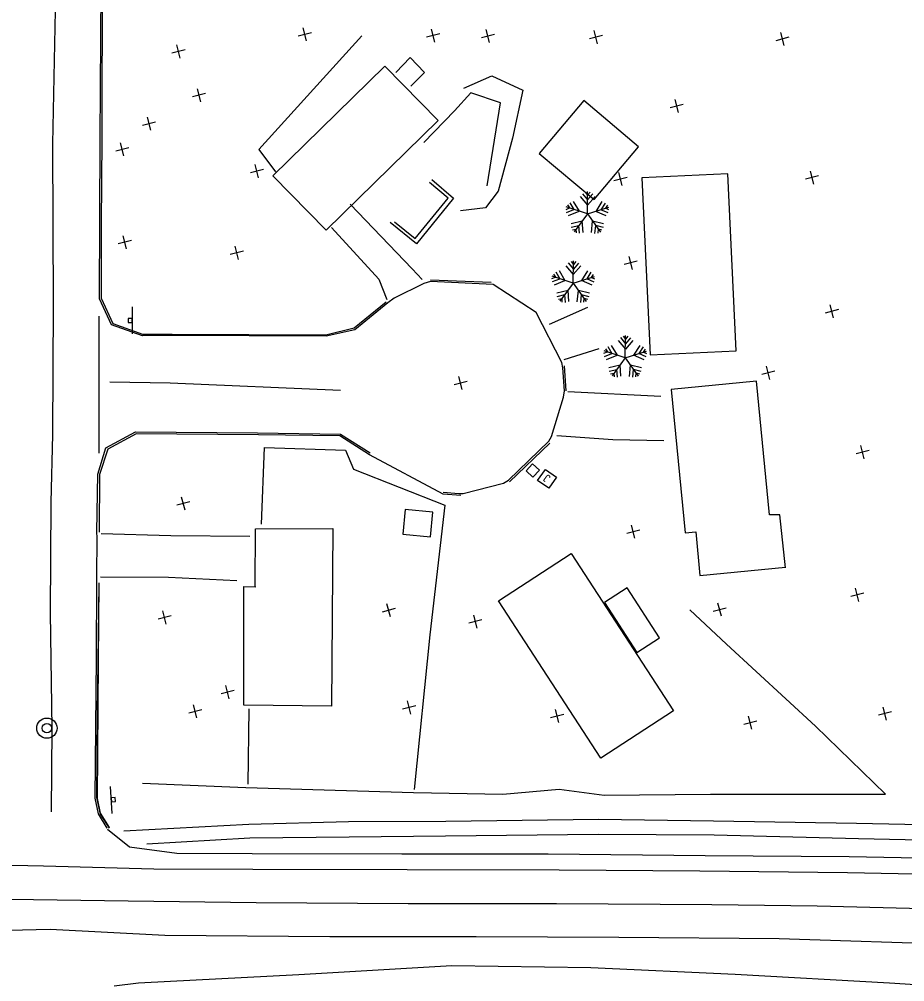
# Model space of a CAD drawing. Extents: x 4711259 to 4716401, y 890074 to 892728.
# Drawn here: x 4714377.1 to 4714704.2, y 891318.6 to 891674.4 of the extents above; entities that cross this region are included whole.
import ezdxf

# ---------------------------------------------------------------- set-up
doc = ezdxf.new("R2010")
doc.units = 0
for name, color, linetype in [('E_HY_STORM_MH', 7, 'Continuous'), ('E_LDSC_VEG_Conifer', 7, 'Continuous'), ('E_RDWY_PHOTOG_Eave', 7, 'Continuous'), ('E_RDWY_PHOTOG_Fence', 7, 'Continuous'), ('E_RDWY_ROAD_Approach', 7, 'Continuous'), ('E_RDWY_ROAD_Curb', 7, 'Continuous'), ('E_RDWY_ROAD_EdgeAsph', 7, 'Continuous'), ('E_RDWY_ROAD_Striping', 7, 'Continuous'), ('E_RDWY_ROAD_TBofCurb', 7, 'Continuous'), ('E_TERR_DTM_BrkLines', 7, 'Continuous'), ('E_TERR_DTM_RandomPt', 7, 'Continuous'), ('E_TRAF_SIGN_PrivateSign', 7, 'Continuous'), ('E_TRAF_SIGN_PublicSign', 7, 'Continuous'), ('E_UTIL_COMM_General', 7, 'Continuous'), ('E_UTIL_ELEC_GENERAL', 7, 'Continuous')]:
    doc.layers.add(name, color=color, linetype=linetype)

msp = doc.modelspace()

# ---------------------------------------------------------------- linework, layer by layer
at = {"layer": 'E_HY_STORM_MH'}
for radius in [3.75, 1.76]:
    msp.add_circle((4714387.27, 891412.37), radius, dxfattribs=at)
at = {"layer": 'E_LDSC_VEG_Conifer'}
for p, q in [((4714584.31, 891608.92), (4714587.03, 891605.69)), ((4714585.17, 891609.95), (4714587.05, 891607.72)), ((4714586.18, 891610.49), (4714587.06, 891609.44)), ((4714587, 891602.46), (4714587.07, 891610.71)), ((4714589.8, 891608.87), (4714587.03, 891605.69)), ((4714588.96, 891609.91), (4714587.05, 891607.72)), ((4714587.97, 891610.48), (4714587.06, 891609.44)), ((4714579.11, 891604.16), (4714580.38, 891604.68)), ((4714587, 891602.46), (4714579.18, 891605.08)), ((4714579.32, 891603.04), (4714582.02, 891604.13)), ((4714579.68, 891605.86), (4714580.38, 891604.68)), ((4714580.52, 891606.63), (4714582.02, 891604.13)), ((4714581.77, 891607.11), (4714583.94, 891603.49)), ((4714587, 891602.46), (4714594.87, 891604.94)), ((4714592.31, 891607.02), (4714590.08, 891603.43)), ((4714593.55, 891606.51), (4714592.01, 891604.04)), ((4714594.69, 891602.9), (4714592.01, 891604.04)), ((4714594.38, 891605.73), (4714593.66, 891604.56)), ((4714594.92, 891604.02), (4714593.66, 891604.56)), ((4714580.03, 891601.9), (4714583.94, 891603.49)), ((4714587, 891602.46), (4714582.09, 891595.83)), ((4714587, 891602.46), (4714591.79, 891595.75)), ((4714593.96, 891601.78), (4714590.08, 891603.43)), ((4714580.96, 891598.93), (4714585.08, 891599.87)), ((4714581.03, 891597.59), (4714583.87, 891598.24)), ((4714581.51, 891596.55), (4714582.85, 891596.85)), ((4714582.94, 891595.48), (4714582.85, 891596.85)), ((4714584.08, 891595.34), (4714583.87, 891598.24)), ((4714585.38, 891595.66), (4714585.08, 891599.87)), ((4714588.5, 891595.63), (4714588.87, 891599.83)), ((4714592.97, 891598.82), (4714588.87, 891599.83)), ((4714589.79, 891595.28), (4714590.05, 891598.18)), ((4714592.88, 891597.48), (4714590.05, 891598.18)), ((4714590.93, 891595.41), (4714591.05, 891596.78)), ((4714592.38, 891596.45), (4714591.05, 891596.78)), ((4714579.07, 891583.31), (4714581.79, 891580.08)), ((4714579.93, 891584.34), (4714581.81, 891582.11)), ((4714580.94, 891584.88), (4714581.82, 891583.83)), ((4714581.76, 891576.85), (4714581.84, 891585.1)), ((4714584.57, 891583.26), (4714581.79, 891580.08)), ((4714583.72, 891584.3), (4714581.81, 891582.11)), ((4714582.73, 891584.87), (4714581.82, 891583.83)), ((4714573.87, 891578.55), (4714575.14, 891579.07)), ((4714581.76, 891576.85), (4714573.94, 891579.47)), ((4714574.44, 891580.25), (4714575.14, 891579.07)), ((4714575.28, 891581.02), (4714576.78, 891578.52)), ((4714576.53, 891581.5), (4714578.7, 891577.88)), ((4714581.76, 891576.85), (4714589.63, 891579.33)), ((4714587.07, 891581.41), (4714584.84, 891577.82)), ((4714588.31, 891580.9), (4714586.77, 891578.43)), ((4714589.14, 891580.12), (4714588.42, 891578.95)), ((4714589.68, 891578.41), (4714588.42, 891578.95)), ((4714574.08, 891577.43), (4714576.78, 891578.52)), ((4714574.79, 891576.29), (4714578.7, 891577.88)), ((4714581.76, 891576.85), (4714576.85, 891570.22)), ((4714581.76, 891576.85), (4714586.55, 891570.14)), ((4714588.72, 891576.17), (4714584.84, 891577.82)), ((4714589.45, 891577.29), (4714586.77, 891578.43)), ((4714575.73, 891573.32), (4714579.84, 891574.26)), ((4714575.8, 891571.98), (4714578.63, 891572.63)), ((4714578.84, 891569.73), (4714578.63, 891572.63)), ((4714580.14, 891570.05), (4714579.84, 891574.26)), ((4714583.26, 891570.02), (4714583.64, 891574.22)), ((4714587.73, 891573.21), (4714583.64, 891574.22)), ((4714584.55, 891569.68), (4714584.81, 891572.58)), ((4714587.64, 891571.88), (4714584.81, 891572.58)), ((4714576.27, 891570.94), (4714577.61, 891571.25)), ((4714577.71, 891569.88), (4714577.61, 891571.25)), ((4714585.69, 891569.8), (4714585.81, 891571.17)), ((4714587.15, 891570.84), (4714585.81, 891571.17)), ((4714598.31, 891555.7), (4714601.03, 891552.48)), ((4714599.17, 891556.73), (4714601.04, 891554.5)), ((4714600.17, 891557.28), (4714601.06, 891556.22)), ((4714601, 891549.25), (4714601.07, 891557.5)), ((4714603.8, 891555.65), (4714601.03, 891552.48)), ((4714602.96, 891556.69), (4714601.04, 891554.5)), ((4714601.96, 891557.26), (4714601.06, 891556.22)), ((4714593.11, 891550.95), (4714594.38, 891551.46)), ((4714601, 891549.25), (4714593.17, 891551.87)), ((4714593.32, 891549.82), (4714596.01, 891550.92)), ((4714593.67, 891552.64), (4714594.38, 891551.46)), ((4714594.52, 891553.41), (4714596.01, 891550.92)), ((4714595.77, 891553.89), (4714597.93, 891550.27)), ((4714601, 891549.25), (4714608.86, 891551.72)), ((4714606.31, 891553.8), (4714604.08, 891550.22)), ((4714607.55, 891553.3), (4714606.01, 891550.83)), ((4714608.69, 891549.68), (4714606.01, 891550.83)), ((4714608.38, 891552.51), (4714607.65, 891551.34)), ((4714608.92, 891550.8), (4714607.65, 891551.34)), ((4714594.02, 891548.69), (4714597.93, 891550.27)), ((4714601, 891549.25), (4714596.09, 891542.62)), ((4714601, 891549.25), (4714605.78, 891542.53)), ((4714607.96, 891548.56), (4714604.08, 891550.22)), ((4714594.96, 891545.71), (4714599.07, 891546.65)), ((4714595.03, 891544.37), (4714597.87, 891545.02)), ((4714595.5, 891543.33), (4714596.84, 891543.64)), ((4714596.94, 891542.27), (4714596.84, 891543.64)), ((4714598.08, 891542.12), (4714597.87, 891545.02)), ((4714599.37, 891542.44), (4714599.07, 891546.65)), ((4714602.49, 891542.41), (4714602.87, 891546.62)), ((4714606.97, 891545.6), (4714602.87, 891546.62)), ((4714603.79, 891542.07), (4714604.05, 891544.97)), ((4714606.87, 891544.27), (4714604.05, 891544.97)), ((4714604.92, 891542.2), (4714605.05, 891543.56)), ((4714606.38, 891543.23), (4714605.05, 891543.56))]:
    msp.add_line(p, q, dxfattribs=at)
at = {"layer": 'E_RDWY_PHOTOG_Eave'}
for points in [[(4714490.47, 891596.47), (4714531.89, 891637.01), (4714512.19, 891657.14), (4714470.77, 891616.6)], [(4714605.91, 891627.33), (4714585.64, 891644.36), (4714569.19, 891624.78), (4714589.47, 891607.75)], [(4714641.93, 891551.88), (4714638.85, 891617.28), (4714607.11, 891615.79), (4714610.19, 891550.38)], [(4714529.01, 891483.06), (4714529.86, 891492.25), (4714519.63, 891493.24), (4714518.78, 891484.05)], [(4714580.95, 891476.9), (4714618.82, 891418.8), (4714591.97, 891401.3), (4714554.11, 891459.4)], [(4714605.25, 891440.36), (4714613.57, 891445.72), (4714601.66, 891464.21), (4714593.34, 891458.85)]]:
    msp.add_lwpolyline(points, close=True, dxfattribs=at)
for points in [[(4714521.75, 891649.65), (4714526.78, 891654.7), (4714521.49, 891660.3), (4714516.24, 891654.78)], [(4714660.24, 891471.61), (4714658.05, 891491.22), (4714654.27, 891491.25), (4714649.44, 891540.59), (4714617.99, 891537.57), (4714623.08, 891484.58), (4714627.04, 891484.93), (4714628.54, 891468.8), (4714660.22, 891471.86)], [(4714464.27, 891464.89), (4714464.33, 891486.09), (4714492.94, 891486.14), (4714492.45, 891420.53), (4714460.06, 891420.83), (4714460.07, 891464.68), (4714464.49, 891464.63)]]:
    msp.add_lwpolyline(points, dxfattribs=at)
at = {"layer": 'E_RDWY_PHOTOG_Fence'}
for points in [[(4714503.65, 891668.32), (4714465.54, 891626.27), (4714471.79, 891618.04)], [(4714466.58, 891487.79), (4714467.68, 891516.17), (4714497.58, 891515.2), (4714500.62, 891508.08), (4714534.35, 891494.76), (4714528.77, 891446.9), (4714522.98, 891389.69)], [(4714422.64, 891392.08), (4714460.84, 891390.46), (4714522.73, 891388.56), (4714555.79, 891388), (4714576.61, 891389.81), (4714593.19, 891387.6), (4714632.51, 891388.02), (4714685.93, 891387.99), (4714697.19, 891388), (4714671.25, 891413.1), (4714638.37, 891443.43), (4714624.79, 891456.11)], [(4714461.83, 891419.46), (4714461.46, 891391.65)]]:
    msp.add_lwpolyline(points, dxfattribs=at)
at = {"layer": 'E_RDWY_ROAD_Approach'}
for points in [[(4714525.99, 891578.27), (4714522.25, 891582.18), (4714499.36, 891606.03)], [(4714492.42, 891597.45), (4714509.97, 891578.37), (4714512.9, 891570.86)], [(4714573, 891561.75), (4714587.1, 891568.03)], [(4714578.45, 891548.65), (4714591.35, 891552.68)], [(4714579.81, 891536.81), (4714614.17, 891535.15)], [(4714615.2, 891518.57), (4714596.41, 891519.02), (4714575.71, 891520.49)], [(4714462.23, 891483.21), (4714433.08, 891483.52), (4714407.35, 891484.21)], [(4714407.06, 891468.26), (4714432.23, 891468.17), (4714457.51, 891466.94)]]:
    msp.add_lwpolyline(points, dxfattribs=at)
at = {"layer": 'E_RDWY_ROAD_Curb'}
for points in [[(4714533.73, 891499.62), (4714539.52, 891499.17), (4714541.11, 891499.11), (4714556, 891502.95), (4714557.79, 891504.01), (4714572.77, 891518.43), (4714573.71, 891520.25), (4714578.19, 891534.68), (4714578.49, 891537.04), (4714577.97, 891545.57), (4714577.53, 891547.56), (4714568.04, 891566.02), (4714552.22, 891576.37), (4714528.99, 891577.44), (4714526.49, 891576.78), (4714515.54, 891571.35), (4714513.29, 891569.62), (4714501, 891559.68), (4714490.42, 891557.34), (4714433.52, 891557.53), (4714422.62, 891557.46), (4714411.13, 891561.45), (4714406.73, 891571.1), (4714406.94, 891630.31), (4714407.29, 891685.99)], [(4714409.6, 891375.36), (4714406.29, 891380.71), (4714405.17, 891386.51), (4714405.59, 891438.33), (4714405.71, 891466.55), (4714405.73, 891468.4), (4714405.84, 891482.74), (4714405.76, 891485.01), (4714406.05, 891506.25), (4714409.04, 891516.06), (4714420.01, 891521.94), (4714465.15, 891521.58), (4714495.79, 891521.05), (4714506.75, 891514.19)]]:
    msp.add_lwpolyline(points, dxfattribs=at)
at = {"layer": 'E_RDWY_ROAD_EdgeAsph'}
for points in [[(4714928.91, 891677.41), (4714927.35, 891627.44), (4714926.44, 891566.8), (4714921.46, 891514.05), (4714910.32, 891470.49), (4714895.76, 891428.7), (4714878.11, 891394.18), (4714864.84, 891368.83), (4714860.55, 891364.18), (4714841.33, 891355.8), (4714793.66, 891360.05), (4714747.59, 891363.54), (4714683.67, 891364.81), (4714630.51, 891365.23), (4714572.54, 891365.83), (4714518.44, 891365.84), (4714463.12, 891365.94), (4714435.29, 891366.09), (4714417.84, 891368.4), (4714409.72, 891374.94)], [(4714415.74, 891374.4), (4714461.85, 891376.82), (4714498.77, 891377.84), (4714534.66, 891378.01), (4714591.12, 891378.76), (4714633.6, 891378.15), (4714686.47, 891377.31), (4714716.2, 891376.61), (4714767.71, 891373.51), (4714805.69, 891368.04), (4714847.87, 891364.5), (4714859, 891364.41)], [(4714846.73, 891359.86), (4714805.04, 891363.71), (4714766.34, 891367.95), (4714715.85, 891370.82), (4714687.17, 891371.47), (4714633.85, 891372.79), (4714590.92, 891373.1), (4714534.59, 891372.39), (4714498.91, 891372.09), (4714462.23, 891371.73), (4714424.23, 891369.49)], [(4714412.07, 891317.13), (4714421.12, 891318.22), (4714480.4, 891321.25), (4714536.91, 891324.63), (4714588.2, 891323.89), (4714641.59, 891321.38), (4714698.61, 891318.18), (4714754.2, 891314.67), (4714804.09, 891311.59), (4714810.85, 891309.49), (4714814.29, 891305.29)]]:
    msp.add_lwpolyline(points, dxfattribs=at)
at = {"layer": 'E_RDWY_ROAD_Striping'}
for points in [[(4714842.47, 891350.26), (4714800.39, 891354.16), (4714739.26, 891357.79), (4714683.08, 891358.93), (4714628.59, 891359.56), (4714576.52, 891359.85), (4714520.41, 891360.06), (4714463.34, 891360.15), (4714426.81, 891360.19)], [(4714417.33, 891348.49), (4714464.54, 891347.92), (4714520.78, 891347.61), (4714575.54, 891347.51), (4714633, 891347.21), (4714671.94, 891346.72), (4714740.14, 891344.96), (4714794.04, 891341.29), (4714825.14, 891337.47)], [(4714430.85, 891335.81), (4714491.82, 891335.4), (4714545.94, 891335.3), (4714598.63, 891335.16), (4714657.9, 891334.59), (4714725.97, 891332.45)]]:
    msp.add_lwpolyline(points, dxfattribs=at)
at = {"layer": 'E_RDWY_ROAD_TBofCurb'}
for points in [[(4714408, 891707.18), (4714407.82, 891685.93), (4714407.6, 891652.58), (4714407.56, 891630.14), (4714407.33, 891598.72), (4714407.29, 891571.32), (4714411.62, 891561.94), (4714422.61, 891558.04), (4714433.51, 891558.02), (4714490.31, 891557.78), (4714500.83, 891560.36), (4714512.66, 891569.93)], [(4714528.98, 891578.08), (4714551.43, 891577.23)], [(4714578.36, 891546.35), (4714579.06, 891537.03)], [(4714533.66, 891498.9), (4714506.51, 891513.46), (4714495.56, 891520.43), (4714465.45, 891520.77), (4714420.31, 891521.21), (4714409.74, 891515.53), (4714406.69, 891506.09), (4714406.58, 891484.78)], [(4714573.1, 891517.73), (4714558.16, 891503.47)], [(4714540.23, 891498.43), (4714533.66, 891498.9)], [(4714406.46, 891465.79), (4714405.88, 891417.64), (4714405.59, 891386.74), (4714406.9, 891380.57), (4714410.24, 891375.39)], [(4714406.52, 891466.09), (4714406.27, 891437.22), (4714405.89, 891386.31), (4714406.98, 891380.93), (4714410.24, 891375.67)]]:
    msp.add_lwpolyline(points, dxfattribs=at)
at = {"layer": 'E_TERR_DTM_BrkLines'}
for points in [[(4714388.98, 891381.46), (4714389.18, 891412.24), (4714388.56, 891455.05), (4714388.86, 891495.74), (4714389.44, 891520.88), (4714389.73, 891568.87), (4714389.47, 891628.36), (4714390.44, 891677.73), (4714389.95, 891712.3)], [(4714541.27, 891649.01), (4714551.68, 891653.58), (4714563.14, 891648.2), (4714559.28, 891630.42), (4714553.96, 891610.84), (4714549.31, 891604.73), (4714540.04, 891603.61)], [(4714549.98, 891612.81), (4714554.84, 891643.53), (4714543.87, 891647.19), (4714537.87, 891640.58), (4714526.57, 891628.9)], [(4714529.53, 891615.17), (4714537.57, 891608.29), (4714523.82, 891591.46), (4714514.14, 891599.3)], [(4714515.67, 891599.6), (4714523.4, 891593.4), (4714535.51, 891608.29), (4714528.63, 891614.12)], [(4714406.64, 891514), (4714406.53, 891537.66), (4714406.63, 891564.65)], [(4714495.7, 891537.17), (4714432.81, 891539.93), (4714410.53, 891540.31)], [(4714426.81, 891360.19), (4714385.97, 891361.37), (4714344.96, 891362.21)], [(4714346.02, 891349.33), (4714382.34, 891348.99), (4714417.33, 891348.49)], [(4714352.47, 891337.17), (4714388.51, 891338.06), (4714430.85, 891335.81)]]:
    msp.add_lwpolyline(points, dxfattribs=at)
at = {"layer": 'E_TERR_DTM_RandomPt'}
for p, q in [((4714484.99, 891669.44), (4714480.15, 891668.19)), ((4714483.19, 891666.4), (4714481.94, 891671.24)), ((4714532.43, 891669.01), (4714527.59, 891667.76)), ((4714530.63, 891665.96), (4714529.38, 891670.81)), ((4714552.66, 891668.83), (4714547.82, 891667.58)), ((4714550.86, 891665.79), (4714549.61, 891670.63)), ((4714592.57, 891668.44), (4714587.73, 891667.19)), ((4714590.77, 891665.39), (4714589.52, 891670.24)), ((4714659.66, 891664.71), (4714658.41, 891669.55)), ((4714436.54, 891660.09), (4714435.29, 891664.93)), ((4714661.45, 891667.76), (4714656.61, 891666.51)), ((4714438.34, 891663.13), (4714433.5, 891661.88)), ((4714445.92, 891646.95), (4714441.08, 891645.7)), ((4714444.13, 891643.9), (4714442.88, 891648.74)), ((4714622.42, 891642.98), (4714617.58, 891641.73)), ((4714620.63, 891639.93), (4714619.38, 891644.77)), ((4714427.43, 891636.45), (4714422.59, 891635.2)), ((4714425.64, 891633.4), (4714424.39, 891638.24)), ((4714415.76, 891623.92), (4714414.51, 891628.76)), ((4714417.56, 891626.96), (4714412.71, 891625.71)), ((4714467.29, 891618.91), (4714462.45, 891617.66)), ((4714465.5, 891615.87), (4714464.25, 891620.71)), ((4714670.64, 891613.46), (4714669.39, 891618.3)), ((4714601.65, 891615.97), (4714596.81, 891614.72)), ((4714599.85, 891612.93), (4714598.6, 891617.77)), ((4714672.43, 891616.51), (4714667.59, 891615.26)), ((4714416.72, 891589.57), (4714415.47, 891594.41)), ((4714418.52, 891592.61), (4714413.67, 891591.36)), ((4714458.07, 891585.67), (4714456.82, 891590.51)), ((4714459.87, 891588.71), (4714455.03, 891587.46)), ((4714603.61, 891581.95), (4714602.36, 891586.79)), ((4714605.41, 891585), (4714600.57, 891583.75)), ((4714677.93, 891564.04), (4714676.68, 891568.88)), ((4714679.72, 891567.09), (4714674.88, 891565.84)), ((4714656.23, 891544.37), (4714651.39, 891543.12)), ((4714654.43, 891541.32), (4714653.18, 891546.16)), ((4714542.57, 891540.58), (4714537.72, 891539.33)), ((4714540.77, 891537.53), (4714539.52, 891542.37)), ((4714691.08, 891515.02), (4714686.24, 891513.77)), ((4714689.29, 891511.97), (4714688.04, 891516.81)), ((4714438.31, 891492.97), (4714437.05, 891497.81)), ((4714440.1, 891496.01), (4714435.26, 891494.76)), ((4714604.57, 891482.56), (4714603.32, 891487.4)), ((4714606.37, 891485.6), (4714601.53, 891484.35)), ((4714689.13, 891462.28), (4714684.29, 891461.03)), ((4714687.34, 891459.24), (4714686.09, 891464.08)), ((4714514.18, 891453.52), (4714512.93, 891458.36)), ((4714636.48, 891453.74), (4714635.23, 891458.58)), ((4714431.38, 891450.86), (4714430.13, 891455.7)), ((4714515.97, 891456.56), (4714511.13, 891455.31)), ((4714638.27, 891456.78), (4714633.43, 891455.53)), ((4714433.18, 891453.91), (4714428.33, 891452.66)), ((4714548.02, 891452.38), (4714543.18, 891451.13)), ((4714546.22, 891449.33), (4714544.97, 891454.17)), ((4714456.48, 891426.3), (4714451.64, 891425.05)), ((4714454.68, 891423.25), (4714453.43, 891428.09)), ((4714521.77, 891417.58), (4714520.51, 891422.42)), ((4714444.5, 891419.2), (4714439.66, 891417.95)), ((4714442.71, 891416.16), (4714441.46, 891421)), ((4714523.56, 891420.62), (4714518.72, 891419.37)), ((4714576.45, 891414.42), (4714575.2, 891419.26)), ((4714697.53, 891415.32), (4714696.28, 891420.17)), ((4714578.24, 891417.47), (4714573.4, 891416.22)), ((4714647.77, 891411.95), (4714646.52, 891416.79)), ((4714699.33, 891418.37), (4714694.49, 891417.12)), ((4714649.57, 891415), (4714644.73, 891413.75))]:
    msp.add_line(p, q, dxfattribs=at)
at = {"layer": 'E_TRAF_SIGN_PrivateSign'}
for p, q in [((4714411.37, 891380.88), (4714410.72, 891390.86)), ((4714411.79, 891385.92), (4714411.79, 891385.92))]:
    msp.add_line(p, q, dxfattribs=at)
msp.add_lwpolyline([(4714411.09, 891385.12), (4714412.59, 891385.22), (4714412.49, 891386.72), (4714410.99, 891386.62)], close=True, dxfattribs=at)
at = {"layer": 'E_TRAF_SIGN_PublicSign'}
for p, q in [((4714418.74, 891568.12), (4714418.83, 891558.12)), ((4714418.03, 891563.11), (4714418.03, 891563.11))]:
    msp.add_line(p, q, dxfattribs=at)
msp.add_lwpolyline([(4714418.78, 891563.87), (4714417.28, 891563.85), (4714417.29, 891562.35), (4714418.79, 891562.37)], close=True, dxfattribs=at)
at = {"layer": 'E_UTIL_COMM_General'}
msp.add_lwpolyline([(4714566.88, 891505.14), (4714564.31, 891507.52), (4714566.69, 891510.09), (4714569.26, 891507.71)], close=True, dxfattribs=at)
at = {"layer": 'E_UTIL_ELEC_GENERAL'}
msp.add_lwpolyline([(4714571.46, 891508.04), (4714575.55, 891505.16), (4714572.68, 891501.07), (4714568.59, 891503.95)], close=True, dxfattribs=at)

# ---------------------------------------------------------------- texts
msp.add_text('J', height=3, rotation=144.8996, dxfattribs=at).set_placement((4714573.66, 891505.35))

doc.saveas('drawing.dxf')
